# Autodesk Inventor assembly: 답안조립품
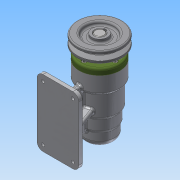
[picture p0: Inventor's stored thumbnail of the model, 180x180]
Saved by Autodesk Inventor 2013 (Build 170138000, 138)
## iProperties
Created: 2016-06
Part Number: 답안조립품
Document SubType Name: Assembly
Designer: Administrator
Author: Administrator
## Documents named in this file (12)
- C:\Users\Administrator\Desktop\460608V1026\답안조립품.iam
- C:\Users\Administrator\Desktop\460608V1026\V벨트풀리.ipt
- C:\Users\Administrator\Desktop\460608V1026\멈춤나사 M3x8.ipt
- C:\Users\Administrator\Desktop\460608V1026\베어링 6004.ipt
- C:\Users\Administrator\Desktop\460608V1026\베어링 51202.ipt
- C:\Users\Administrator\Desktop\460608V1026\본체.ipt
- C:\Users\Administrator\Desktop\460608V1026\볼트 M4 x 12.ipt
- C:\Users\Administrator\Desktop\460608V1026\어댑터슬리브.ipt
- C:\Users\Administrator\Desktop\460608V1026\오일 실.ipt
- C:\Users\Administrator\Desktop\460608V1026\축.ipt
- C:\Users\Administrator\Desktop\460608V1026\커버.ipt
- C:\Users\Administrator\Desktop\460608V1026\키 5 x 5 x 16.ipt
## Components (6 placed, 2 different names)
1. V벨트풀리:1
2. ISO 4762 M4 x 12:5
3. ISO 4762 M4 x 12:1
4. ISO 4762 M4 x 12:2
5. ISO 4762 M4 x 12:3
6. ISO 4762 M4 x 12:4
